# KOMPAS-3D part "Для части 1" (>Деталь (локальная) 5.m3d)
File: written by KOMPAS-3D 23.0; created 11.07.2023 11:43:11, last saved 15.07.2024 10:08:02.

Document properties: Автор: Владимир; Полное имя файла: C:\Users\YNA_NN\AppData\Local\Temp\KOMPAS-3D\ktf9-da6a-6aee-d98b\_Деталь (локальная) 5.m3d

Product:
- Body: Для части 1
    Материал: Сталь 3сп ГОСТ 380-2005 (density 7850 kg/m3)
    Масса: 157
- Part/product: Для части 1
    Материал: Сталь 3сп ГОСТ 380-2005 (density 7850 kg/m3)
    Масса: 157

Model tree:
1. Эскиз:1
2. Элемент выдавливания:1  (labels: Сталь 3сп ГОСТ 380-2005)
     Расстояние 1 = 100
